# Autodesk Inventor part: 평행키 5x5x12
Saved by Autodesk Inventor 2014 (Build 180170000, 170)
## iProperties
Created: 2025-02
Part Number: 평행키 5x5x12
Material: 강철, 연강
Document SubType Name: Modeling
Designer: dg
Density: 7.86 g/cm^3
Appearance: 강철
Mass: 2.11085 g
Surface Area: 2.43471 cm^2
Volume: 0.268556 cm^3
Author: jhkim
Description: 키 및 해당 키홈
Creation Date: 2025-01-06
Sending System: Autodesk Inventor 2025
Preprocessor: ST-DEVELOPER v20
Author: dg
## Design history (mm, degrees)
node "평행키 5x5x121"
body "Solid1"
node "기준1"
